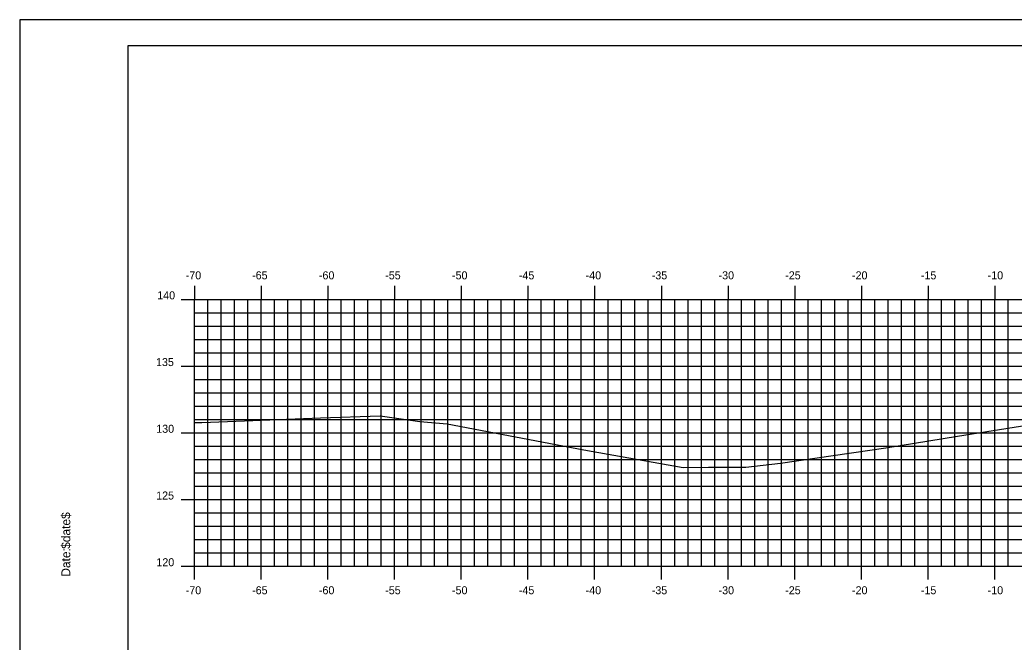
# Model space of a CAD drawing. Extents: x 850630 to 850801, y 365624 to 365734.
# Drawn here: x 850629.6 to 850704.2, y 365687.3 to 365734 of the extents above; entities that cross this region are included whole.
import ezdxf

# ---------------------------------------------------------------- set-up
doc = ezdxf.new("R2010")
doc.units = 0
for name, color, linetype in [('BORDER', 7, 'Continuous'), ('H_V ANNOTATION', 7, 'Continuous'), ('MAJOR', 7, 'Continuous'), ('MINOR', 7, 'Continuous'), ('PLOT BOUNDARY', 7, 'Continuous'), ('S_Roadway_Centerline', 7, 'Continuous')]:
    doc.layers.add(name, color=color, linetype=linetype)

msp = doc.modelspace()

# ---------------------------------------------------------------- linework, layer by layer
at = {"layer": 'BORDER'}
msp.add_lwpolyline([(850637.74, 365627.027), (850797.74, 365627.027), (850797.74, 365732.027), (850637.74, 365732.027)], close=True, dxfattribs=at)
at = {"layer": 'MAJOR'}
for p, q in [((850642.739, 365714.029), (850642.739, 365713.027)), ((850647.739, 365714.029), (850647.739, 365713.027)), ((850652.739, 365714.029), (850652.739, 365713.027)), ((850657.739, 365714.029), (850657.739, 365713.027)), ((850662.739, 365714.029), (850662.739, 365713.027)), ((850667.739, 365714.029), (850667.739, 365713.027)), ((850672.739, 365714.029), (850672.739, 365713.027)), ((850677.739, 365714.029), (850677.739, 365713.027)), ((850682.739, 365714.029), (850682.739, 365713.027)), ((850687.739, 365714.029), (850687.739, 365713.027)), ((850692.739, 365714.029), (850692.739, 365713.027)), ((850697.739, 365714.029), (850697.739, 365713.027)), ((850702.739, 365714.029), (850702.739, 365713.027)), ((850641.737, 365713.027), (850642.739, 365713.027)), ((850642.739, 365713.027), (850782.739, 365713.027)), ((850642.739, 365693.027), (850642.739, 365713.027)), ((850642.739, 365693.027), (850642.739, 365713.027)), ((850642.739, 365713.027), (850782.739, 365713.027)), ((850647.739, 365693.027), (850647.739, 365713.027)), ((850652.739, 365693.027), (850652.739, 365713.027)), ((850657.739, 365693.027), (850657.739, 365713.027)), ((850662.739, 365693.027), (850662.739, 365713.027)), ((850667.739, 365693.027), (850667.739, 365713.027)), ((850672.739, 365693.027), (850672.739, 365713.027)), ((850677.739, 365693.027), (850677.739, 365713.027)), ((850682.739, 365693.027), (850682.739, 365713.027)), ((850687.739, 365693.027), (850687.739, 365713.027)), ((850692.739, 365693.027), (850692.739, 365713.027)), ((850697.739, 365693.027), (850697.739, 365713.027)), ((850702.739, 365693.027), (850702.739, 365713.027)), ((850641.737, 365708.027), (850642.739, 365708.027)), ((850642.739, 365708.027), (850782.739, 365708.027)), ((850641.737, 365703.027), (850642.739, 365703.027)), ((850642.739, 365703.027), (850782.739, 365703.027)), ((850641.737, 365698.027), (850642.739, 365698.027)), ((850642.739, 365698.027), (850782.739, 365698.027)), ((850641.737, 365693.027), (850642.739, 365693.027)), ((850642.739, 365693.027), (850782.739, 365693.027)), ((850642.739, 365693.027), (850782.739, 365693.027)), ((850642.739, 365692.025), (850642.739, 365693.027)), ((850647.739, 365692.025), (850647.739, 365693.027)), ((850652.739, 365692.025), (850652.739, 365693.027)), ((850657.739, 365692.025), (850657.739, 365693.027)), ((850662.739, 365692.025), (850662.739, 365693.027)), ((850667.739, 365692.025), (850667.739, 365693.027)), ((850672.739, 365692.025), (850672.739, 365693.027)), ((850677.739, 365692.025), (850677.739, 365693.027)), ((850682.739, 365692.025), (850682.739, 365693.027)), ((850687.739, 365692.025), (850687.739, 365693.027)), ((850692.739, 365692.025), (850692.739, 365693.027)), ((850697.739, 365692.025), (850697.739, 365693.027)), ((850702.739, 365692.025), (850702.739, 365693.027))]:
    msp.add_line(p, q, dxfattribs=at)
at = {"layer": 'MINOR'}
for p, q in [((850643.739, 365693.027), (850643.739, 365713.027)), ((850644.739, 365693.027), (850644.739, 365713.027)), ((850645.739, 365693.027), (850645.739, 365713.027)), ((850646.739, 365693.027), (850646.739, 365713.027)), ((850648.739, 365693.027), (850648.739, 365713.027)), ((850649.739, 365693.027), (850649.739, 365713.027)), ((850650.739, 365693.027), (850650.739, 365713.027)), ((850651.739, 365693.027), (850651.739, 365713.027)), ((850653.739, 365693.027), (850653.739, 365713.027)), ((850654.739, 365693.027), (850654.739, 365713.027)), ((850655.739, 365693.027), (850655.739, 365713.027)), ((850656.739, 365693.027), (850656.739, 365713.027)), ((850658.739, 365693.027), (850658.739, 365713.027)), ((850659.739, 365693.027), (850659.739, 365713.027)), ((850660.739, 365693.027), (850660.739, 365713.027)), ((850661.739, 365693.027), (850661.739, 365713.027)), ((850663.739, 365693.027), (850663.739, 365713.027)), ((850664.739, 365693.027), (850664.739, 365713.027)), ((850665.739, 365693.027), (850665.739, 365713.027)), ((850666.739, 365693.027), (850666.739, 365713.027)), ((850668.739, 365693.027), (850668.739, 365713.027)), ((850669.739, 365693.027), (850669.739, 365713.027)), ((850670.739, 365693.027), (850670.739, 365713.027)), ((850671.739, 365693.027), (850671.739, 365713.027)), ((850673.739, 365693.027), (850673.739, 365713.027)), ((850674.739, 365693.027), (850674.739, 365713.027)), ((850675.739, 365693.027), (850675.739, 365713.027)), ((850676.739, 365693.027), (850676.739, 365713.027)), ((850678.739, 365693.027), (850678.739, 365713.027)), ((850679.739, 365693.027), (850679.739, 365713.027)), ((850680.739, 365693.027), (850680.739, 365713.027)), ((850681.739, 365693.027), (850681.739, 365713.027)), ((850683.739, 365693.027), (850683.739, 365713.027)), ((850684.739, 365693.027), (850684.739, 365713.027)), ((850685.739, 365693.027), (850685.739, 365713.027)), ((850686.739, 365693.027), (850686.739, 365713.027)), ((850688.739, 365693.027), (850688.739, 365713.027)), ((850689.739, 365693.027), (850689.739, 365713.027)), ((850690.739, 365693.027), (850690.739, 365713.027)), ((850691.739, 365693.027), (850691.739, 365713.027)), ((850693.739, 365693.027), (850693.739, 365713.027)), ((850694.739, 365693.027), (850694.739, 365713.027)), ((850695.739, 365693.027), (850695.739, 365713.027)), ((850696.739, 365693.027), (850696.739, 365713.027)), ((850698.739, 365693.027), (850698.739, 365713.027)), ((850699.739, 365693.027), (850699.739, 365713.027)), ((850700.739, 365693.027), (850700.739, 365713.027)), ((850701.739, 365693.027), (850701.739, 365713.027)), ((850703.739, 365693.027), (850703.739, 365713.027)), ((850642.739, 365712.027), (850782.739, 365712.027)), ((850642.739, 365712.027), (850643.741, 365712.027)), ((850642.739, 365711.027), (850782.739, 365711.027)), ((850642.739, 365711.027), (850643.741, 365711.027)), ((850642.739, 365710.027), (850782.739, 365710.027)), ((850642.739, 365710.027), (850643.741, 365710.027)), ((850642.739, 365709.027), (850782.739, 365709.027)), ((850642.739, 365709.027), (850643.741, 365709.027)), ((850642.739, 365707.027), (850782.739, 365707.027)), ((850642.739, 365707.027), (850643.741, 365707.027)), ((850642.739, 365706.027), (850782.739, 365706.027)), ((850642.739, 365706.027), (850643.741, 365706.027)), ((850642.739, 365705.027), (850782.739, 365705.027)), ((850642.739, 365705.027), (850643.741, 365705.027)), ((850642.739, 365704.027), (850782.739, 365704.027)), ((850642.739, 365704.027), (850643.741, 365704.027)), ((850642.739, 365702.027), (850782.739, 365702.027)), ((850642.739, 365702.027), (850643.741, 365702.027)), ((850642.739, 365701.027), (850782.739, 365701.027)), ((850642.739, 365701.027), (850643.741, 365701.027)), ((850642.739, 365700.027), (850782.739, 365700.027)), ((850642.739, 365700.027), (850643.741, 365700.027)), ((850642.739, 365699.027), (850782.739, 365699.027)), ((850642.739, 365699.027), (850643.741, 365699.027)), ((850642.739, 365697.027), (850782.739, 365697.027)), ((850642.739, 365697.027), (850643.741, 365697.027)), ((850642.739, 365696.027), (850782.739, 365696.027)), ((850642.739, 365696.027), (850643.741, 365696.027)), ((850642.739, 365695.027), (850782.739, 365695.027)), ((850642.739, 365695.027), (850643.741, 365695.027)), ((850642.739, 365694.027), (850782.739, 365694.027)), ((850642.739, 365694.027), (850643.741, 365694.027))]:
    msp.add_line(p, q, dxfattribs=at)
at = {"layer": 'PLOT BOUNDARY'}
msp.add_lwpolyline([(850629.646, 365623.968), (850799.646, 365623.968), (850799.646, 365733.968), (850629.646, 365733.968)], close=True, dxfattribs=at)
at = {"layer": 'S_Roadway_Centerline'}
msp.add_lwpolyline([(850642.739, 365703.797), (850643.281, 365703.796), (850643.936, 365703.823), (850652.177, 365704.146), (850656.664, 365704.294), (850659.633, 365703.87), (850661.69, 365703.699), (850671.934, 365701.755), (850679.367, 365700.437), (850681.283, 365700.443), (850684.081, 365700.451), (850686.67, 365700.762), (850694.56, 365701.89), (850699.934, 365702.767), (850708.915, 365704.192)], dxfattribs=at)

# ---------------------------------------------------------------- texts
at = {"layer": 'BORDER'}
for s, p in [('$date$', (850633.425, 365694.332)), ('Date:', (850633.425, 365692.244))]:
    msp.add_text(s, height=0.6696, rotation=90, dxfattribs=at).set_placement(p)
at = {"layer": 'H_V ANNOTATION'}
for s, p in [('-70', (850642.081, 365714.527)), ('-65', (850647.057, 365714.527)), ('-60', (850652.065, 365714.527)), ('-55', (850657.036, 365714.527)), ('-50', (850662.044, 365714.527)), ('-45', (850667.057, 365714.527)), ('-40', (850672.065, 365714.527)), ('-35', (850677.02, 365714.527)), ('-30', (850682.028, 365714.527)), ('-25', (850687.025, 365714.527)), ('-20', (850692.033, 365714.527)), ('-15', (850697.196, 365714.527)), ('-10', (850702.204, 365714.527)), ('140', (850639.944, 365713.027)), ('135', (850639.853, 365708.027)), ('130', (850639.869, 365703.027)), ('125', (850639.864, 365698.027)), ('120', (850639.88, 365693.027)), ('-70', (850642.081, 365690.927)), ('-65', (850647.057, 365690.927)), ('-60', (850652.065, 365690.927)), ('-55', (850657.036, 365690.927)), ('-50', (850662.044, 365690.927)), ('-45', (850667.057, 365690.927)), ('-40', (850672.065, 365690.927)), ('-35', (850677.02, 365690.927)), ('-30', (850682.028, 365690.927)), ('-25', (850687.025, 365690.927)), ('-20', (850692.033, 365690.927)), ('-15', (850697.196, 365690.927)), ('-10', (850702.204, 365690.927))]:
    msp.add_text(s, height=0.6, dxfattribs=at).set_placement(p)
at = {"layer": 'MAJOR'}
msp.add_text('-', height=0.006, dxfattribs=at).set_placement((850642.735, 365693.027))

doc.saveas('drawing.dxf')
